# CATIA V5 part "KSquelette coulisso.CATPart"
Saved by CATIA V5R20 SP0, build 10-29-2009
Part number: K_Squelette coulisso
Bounding box of the stored display mesh (mm): x -50 to 50, y 117.385 to 154.35, z 546.607 to 639.524
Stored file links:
  C:\Users\thinkmotion1\Desktop\Khaled_IAO_Pack2\IAO_2010_1392_rragonneau\CATIA_1392_rragonneau\KSquelette coulisso.CATPart
  D:\Documents\Scolaire\MM2\IAO\Squelette\Product1.CATProduct
  C:\Users\thinkmotion1\Desktop\Khaled_IAO_Pack2\IAO_2010_1392_rragonneau\CATIA_1392_rragonneau\KSquelette de base.CATPart
  C:\Users\thinkmotion1\Desktop\Khaled_IAO_Pack2\IAO_2010_1392_rragonneau\CATIA_1392_rragonneau\KSquelette  bielle.CATPart
  C:\Users\thinkmotion1\Desktop\Khaled_IAO_Pack2\IAO_2010_1392_rragonneau\CATIA_1392_rragonneau\KSquelette bati.CATPart
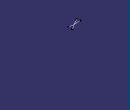
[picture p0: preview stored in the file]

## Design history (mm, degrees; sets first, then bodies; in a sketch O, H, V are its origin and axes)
Set1
  Line1: type Angle, RefPoint Point1, Curve Line4, Support Plane1, Start -50, End 50, Angle 0
  Line2: type PtPt, FirstPoint DatumPoint1, SecondPoint DatumPoint2
Set2
  Plane1: linked copy from another document
  Point1: linked copy from another document
  Line3: linked copy from another document
  DatumPoint1: linked copy from another document
  DatumPoint2: linked copy from another document
  Point2: linked copy from another document
  Line4: linked copy from another document
Body1 (main body)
